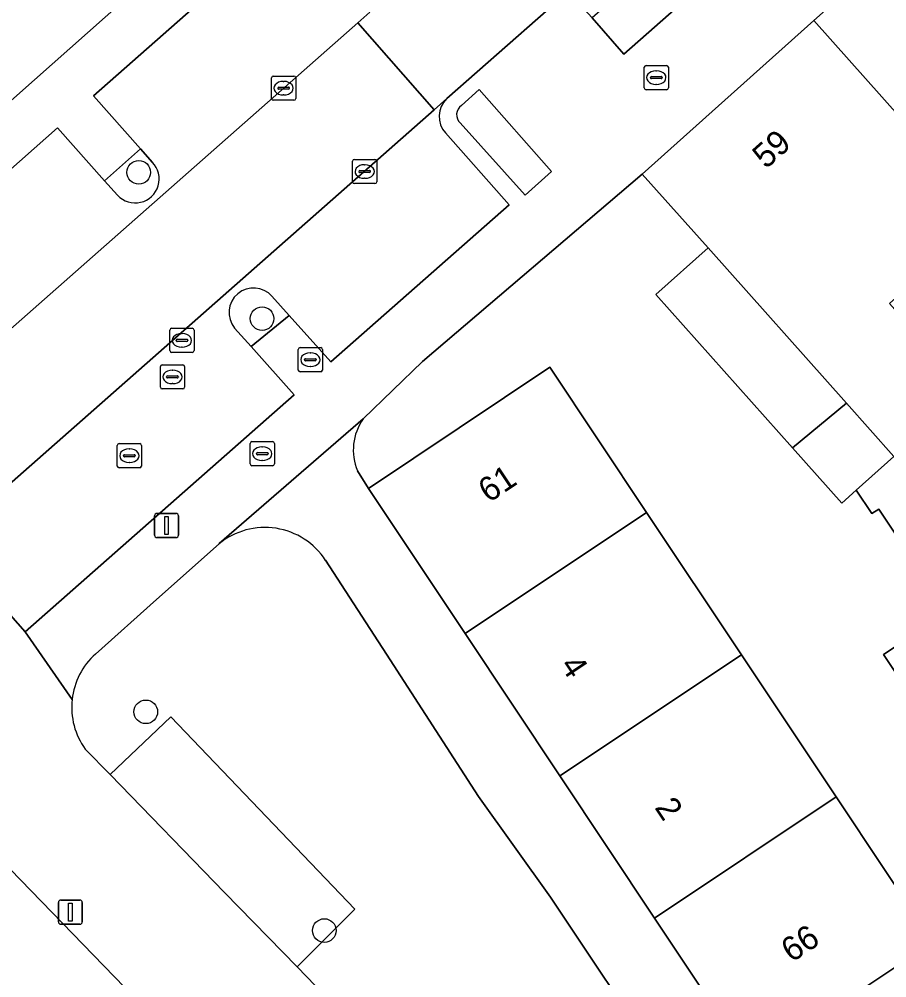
# Model space of a CAD drawing. Extents: x 159960 to 160866, y 382700 to 383354.
# Drawn here: x 160377.49 to 160413.42, y 382879.33 to 382919.01 of the extents above; entities that cross this region are included whole.
import ezdxf

# ---------------------------------------------------------------- set-up
doc = ezdxf.new("R2010")
doc.units = 0
for name, color, linetype in [('IMGEO_Boom', 7, 'Continuous'), ('IMGEO_Brandkraan', 7, 'Continuous'), ('IMGEO_Erf', 7, 'Continuous'), ('IMGEO_Groenvoorziening', 7, 'Continuous'), ('IMGEO_Kolk', 7, 'Continuous'), ('IMGEO_Lichtmast', 7, 'Continuous'), ('IMGEO_Pand', 7, 'Continuous'), ('IMGEO_Pand_nummerreeks', 7, 'Continuous'), ('IMGEO_Parkeervlak_open', 7, 'Continuous'), ('IMGEO_Rijbaan_lokaal_open', 7, 'Continuous'), ('IMGEO_Rioolput', 7, 'Continuous'), ('IMGEO_Voetpad_open', 7, 'Continuous')]:
    doc.layers.add(name, color=color, linetype=linetype)

msp = doc.modelspace()

# ---------------------------------------------------------------- linework, layer by layer
at = {"layer": 'IMGEO_Boom'}
for centre in [(160382.445, 382912.667), (160387.551, 382906.613), (160382.736, 382890.341), (160390.128, 382881.289)]:
    msp.add_circle(centre, 0.489, dxfattribs=at)
at = {"layer": 'IMGEO_Brandkraan'}
for p, q in [((160387.134, 382901.524), (160387.986, 382901.524)), ((160387.059, 382900.598), (160387.059, 382901.45)), ((160387.547, 382901.304), (160387.572, 382901.304)), ((160388.06, 382901.45), (160388.06, 382900.598)), ((160387.318, 382901.018), (160387.318, 382901.03)), ((160387.756, 382900.981), (160387.358, 382900.981)), ((160387.361, 382901.067), (160387.759, 382901.067)), ((160387.57, 382900.744), (160387.545, 382900.744)), ((160387.802, 382901.03), (160387.802, 382901.018)), ((160387.986, 382900.524), (160387.134, 382900.524))]:
    msp.add_line(p, q, dxfattribs=at)
for points in [[(160387.134, 382901.524), (160387.986, 382901.524)], [(160387.059, 382900.598), (160387.059, 382901.45)], [(160388.06, 382901.45), (160388.06, 382900.598)], [(160387.986, 382900.524), (160387.134, 382900.524)]]:
    msp.add_lwpolyline(points, dxfattribs=at)
for centre, radius, start, end in [((160387.136, 382901.448), 0.0765, 91.552, 178.448), ((160387.136, 382901.448), 0.0765, 91.552, 178.448), ((160387.984, 382901.448), 0.0765, 1.552, 88.448), ((160387.984, 382901.448), 0.0765, 1.552, 88.448), ((160387.358, 382901.027), 0.0403, 85.8775, 175.7526), ((160387.355, 382901.017), 0.0366, 178.938, 274.7102), ((160387.759, 382901.024), 0.043, 264.8664, 352.4533), ((160387.763, 382901.029), 0.0386, 1.7309, 96.639), ((160387.136, 382900.6), 0.0765, 181.552, 268.448), ((160387.136, 382900.6), 0.0765, 181.552, 268.448), ((160387.984, 382900.6), 0.0765, 271.552, 358.448), ((160387.984, 382900.6), 0.0765, 271.552, 358.448)]:
    msp.add_arc(centre, radius, start, end, dxfattribs=at)
for centre, major_axis, ratio, start_param, end_param in [((160387.546, 382901.024), (-0.387, 0.002), 0.722429, 4.712389, 7.853982), ((160387.571, 382901.024), (-0.39, 0.002), 0.717154, 1.570796, 4.712389)]:
    msp.add_ellipse(centre, major_axis=major_axis, ratio=ratio, start_param=start_param, end_param=end_param, dxfattribs=at)
at = {"layer": 'IMGEO_Erf'}
for points in [[(160412.146, 382899.51), (160411.554, 382898.982), (160409.515, 382901.266), (160403.856, 382907.606), (160406.019, 382909.536), (160403.288, 382912.595), (160394.188, 382904.838), (160391.732, 382902.464)], [(160391.496, 382900.313), (160391.954, 382899.589), (160399.473, 382904.598), (160403.476, 382898.589), (160407.397, 382892.703), (160411.318, 382886.819), (160415.322, 382880.808), (160408.003, 382875.932), (160409.407, 382875.338)], [(160410.766, 382875.384), (160412.656, 382876.385), (160423.19, 382883.633), (160421.859, 382885.567), (160419.212, 382883.804), (160415.394, 382889.535), (160413.28, 382892.709), (160415.927, 382894.472), (160413.088, 382898.734), (160412.802, 382898.543), (160412.146, 382899.51)]]:
    msp.add_lwpolyline(points, dxfattribs=at)
msp.add_arc((160393.605, 382901.17), 2.276, 145.3568, 202.1207, dxfattribs=at)
at = {"layer": 'IMGEO_Groenvoorziening'}
for points in [[(160366.155, 382905.901), (160381.784, 382919.739)], [(160395.757, 382914.711), (160398.443, 382911.726), (160399.541, 382912.702), (160396.544, 382916.096), (160395.803, 382915.434)], [(160383.011, 382913.08), (160382.519, 382913.635), (160381.031, 382912.321), (160381.57, 382911.719)], [(160386.411, 382906.224), (160387.098, 382905.454), (160388.676, 382906.743), (160387.962, 382907.54)], [(160385.773, 382897.296), (160383.182, 382894.988), (160380.655, 382892.734)], [(160399.496, 382882.677), (160396.518, 382886.833), (160392.707, 382892.722), (160391.172, 382895.093), (160390.183, 382896.611)], [(160380.231, 382888.799), (160381.258, 382887.744), (160383.776, 382890.139), (160391.399, 382882.176), (160389.004, 382879.786), (160390.139, 382878.62), (160398.488, 382870.043)], [(160402.789, 382869.724), (160403.735, 382870.394), (160406.557, 382872.149), (160405.236, 382873.976), (160404.113, 382875.743), (160399.496, 382882.677)]]:
    msp.add_lwpolyline(points, dxfattribs=at)
msp.add_lwpolyline([(160381.258, 382887.744), (160386.001, 382882.871), (160389.004, 382879.786), (160391.399, 382882.176), (160383.776, 382890.139)], close=True, dxfattribs=at)
for centre, radius, start, end in [((160396.068, 382915.054), 0.463, 124.9469, 227.7722), ((160382.299, 382912.391), 0.991, 222.673, 44.0562), ((160387.2, 382906.866), 1.017, 41.4838, 219.1444), ((160387.67, 382894.971), 3, 33.1229, 129.2188), ((160382.623, 382890.529), 2.955, 131.7563, 173.8087), ((160382.612, 382890.531), 2.944, 173.8105, 216.0314)]:
    msp.add_arc(centre, radius, start, end, dxfattribs=at)
at = {"layer": 'IMGEO_Kolk'}
for p, q in [((160403.374, 382916.161), (160403.374, 382917.013)), ((160403.449, 382917.087), (160404.301, 382917.087)), ((160404.375, 382917.013), (160404.375, 382916.161)), ((160387.942, 382915.724), (160387.942, 382916.576)), ((160388.017, 382916.65), (160388.869, 382916.65)), ((160388.943, 382916.576), (160388.943, 382915.724)), ((160403.633, 382916.581), (160403.633, 382916.593)), ((160403.676, 382916.63), (160404.074, 382916.63)), ((160403.862, 382916.867), (160403.887, 382916.867)), ((160404.117, 382916.593), (160404.117, 382916.581)), ((160388.244, 382916.193), (160388.642, 382916.193)), ((160388.43, 382916.43), (160388.455, 382916.43)), ((160404.071, 382916.544), (160403.673, 382916.544)), ((160403.885, 382916.307), (160403.86, 382916.307)), ((160388.201, 382916.144), (160388.201, 382916.156)), ((160388.639, 382916.107), (160388.241, 382916.107)), ((160388.453, 382915.87), (160388.428, 382915.87)), ((160388.685, 382916.156), (160388.685, 382916.144)), ((160404.301, 382916.087), (160403.449, 382916.087)), ((160388.869, 382915.65), (160388.017, 382915.65)), ((160391.3, 382912.275), (160391.3, 382913.127)), ((160391.375, 382913.201), (160392.227, 382913.201)), ((160392.301, 382913.127), (160392.301, 382912.275)), ((160391.559, 382912.695), (160391.559, 382912.707)), ((160391.997, 382912.658), (160391.599, 382912.658)), ((160391.602, 382912.744), (160392, 382912.744)), ((160391.788, 382912.981), (160391.813, 382912.981)), ((160392.043, 382912.707), (160392.043, 382912.695)), ((160392.227, 382912.201), (160391.375, 382912.201)), ((160391.811, 382912.421), (160391.786, 382912.421))]:
    msp.add_line(p, q, dxfattribs=at)
for points in [[(160403.374, 382916.161), (160403.374, 382917.013)], [(160403.449, 382917.087), (160404.301, 382917.087)], [(160404.375, 382917.013), (160404.375, 382916.161)], [(160387.942, 382915.724), (160387.942, 382916.576)], [(160388.017, 382916.65), (160388.869, 382916.65)], [(160388.943, 382916.576), (160388.943, 382915.724)], [(160404.301, 382916.087), (160403.449, 382916.087)], [(160388.869, 382915.65), (160388.017, 382915.65)], [(160391.3, 382912.275), (160391.3, 382913.127)], [(160391.375, 382913.201), (160392.227, 382913.201)], [(160392.301, 382913.127), (160392.301, 382912.275)], [(160392.227, 382912.201), (160391.375, 382912.201)]]:
    msp.add_lwpolyline(points, dxfattribs=at)
for centre, radius, start, end in [((160403.451, 382917.011), 0.0765, 91.552, 178.448), ((160403.451, 382917.011), 0.0765, 91.552, 178.448), ((160404.299, 382917.011), 0.0765, 1.552, 88.448), ((160404.299, 382917.011), 0.0765, 1.552, 88.448), ((160388.019, 382916.574), 0.0765, 91.552, 178.448), ((160388.019, 382916.574), 0.0765, 91.552, 178.448), ((160388.867, 382916.574), 0.0765, 1.552, 88.448), ((160388.867, 382916.574), 0.0765, 1.552, 88.448), ((160403.673, 382916.59), 0.0403, 85.8775, 175.7526), ((160403.67, 382916.58), 0.0366, 178.938, 274.7102), ((160404.074, 382916.587), 0.043, 264.8664, 352.4533), ((160404.078, 382916.592), 0.0386, 1.7309, 96.639), ((160388.241, 382916.153), 0.0403, 85.8775, 175.7526), ((160388.646, 382916.155), 0.0386, 1.7309, 96.639), ((160388.238, 382916.143), 0.0366, 178.938, 274.7102), ((160388.642, 382916.15), 0.043, 264.8664, 352.4533), ((160403.451, 382916.163), 0.0765, 181.552, 268.448), ((160403.451, 382916.163), 0.0765, 181.552, 268.448), ((160404.299, 382916.163), 0.0765, 271.552, 358.448), ((160404.299, 382916.163), 0.0765, 271.552, 358.448), ((160388.019, 382915.726), 0.0765, 181.552, 268.448), ((160388.019, 382915.726), 0.0765, 181.552, 268.448), ((160388.867, 382915.726), 0.0765, 271.552, 358.448), ((160388.867, 382915.726), 0.0765, 271.552, 358.448), ((160391.377, 382913.125), 0.0765, 91.552, 178.448), ((160391.377, 382913.125), 0.0765, 91.552, 178.448), ((160392.225, 382913.125), 0.0765, 1.552, 88.448), ((160392.225, 382913.125), 0.0765, 1.552, 88.448), ((160391.599, 382912.704), 0.0403, 85.8775, 175.7526), ((160391.596, 382912.694), 0.0366, 178.938, 274.7102), ((160392, 382912.701), 0.043, 264.8664, 352.4533), ((160392.004, 382912.706), 0.0386, 1.7309, 96.639), ((160391.377, 382912.277), 0.0765, 181.552, 268.448), ((160391.377, 382912.277), 0.0765, 181.552, 268.448), ((160392.225, 382912.277), 0.0765, 271.552, 358.448), ((160392.225, 382912.277), 0.0765, 271.552, 358.448)]:
    msp.add_arc(centre, radius, start, end, dxfattribs=at)
for centre, major_axis, ratio, start_param, end_param in [((160403.861, 382916.587), (-0.387, 0.002), 0.722429, 4.712389, 7.853982), ((160403.886, 382916.587), (-0.39, 0.002), 0.717154, 1.570796, 4.712389), ((160388.429, 382916.15), (-0.387, 0.002), 0.722429, 4.712389, 7.853982), ((160388.454, 382916.15), (-0.39, 0.002), 0.717154, 1.570796, 4.712389), ((160391.787, 382912.701), (-0.387, 0.002), 0.722429, 4.712389, 7.853982), ((160391.812, 382912.701), (-0.39, 0.002), 0.717154, 1.570796, 4.712389)]:
    msp.add_ellipse(centre, major_axis=major_axis, ratio=ratio, start_param=start_param, end_param=end_param, dxfattribs=at)
at = {"layer": 'IMGEO_Lichtmast'}
for p, q in [((160383.099, 382897.652), (160383.099, 382898.452)), ((160383.099, 382898.452), (160383.099, 382897.652)), ((160383.199, 382898.552), (160383.989, 382898.552)), ((160383.989, 382898.552), (160383.199, 382898.552)), ((160384.089, 382898.452), (160384.089, 382897.652)), ((160384.089, 382897.652), (160384.089, 382898.452)), ((160383.989, 382897.552), (160383.199, 382897.552)), ((160383.199, 382897.552), (160383.989, 382897.552)), ((160379.118, 382881.652), (160379.118, 382882.452)), ((160379.118, 382882.452), (160379.118, 382881.652)), ((160379.218, 382882.552), (160380.008, 382882.552)), ((160380.008, 382882.552), (160379.218, 382882.552)), ((160380.108, 382882.452), (160380.108, 382881.652)), ((160380.108, 382881.652), (160380.108, 382882.452)), ((160380.008, 382881.552), (160379.218, 382881.552)), ((160379.218, 382881.552), (160380.008, 382881.552))]:
    msp.add_line(p, q, dxfattribs=at)
for points in [[(160383.519, 382898.427), (160383.669, 382898.427), (160383.669, 382897.677), (160383.519, 382897.677), (160383.519, 382898.427)], [(160379.538, 382882.427), (160379.688, 382882.427), (160379.688, 382881.677), (160379.538, 382881.677), (160379.538, 382882.427)]]:
    msp.add_lwpolyline(points, dxfattribs=at)
for centre, start, end in [((160383.199, 382898.452), 90, 180), ((160383.199, 382898.452), 90, 180), ((160383.989, 382898.452), 0, 90), ((160383.989, 382898.452), 360, 90), ((160383.199, 382897.652), 180, 270), ((160383.199, 382897.652), 180, 270), ((160383.989, 382897.652), 270, 0), ((160383.989, 382897.652), 270, 0), ((160379.218, 382882.452), 90, 180), ((160379.218, 382882.452), 90, 180), ((160380.008, 382882.452), 0, 90), ((160380.008, 382882.452), 360, 90), ((160379.218, 382881.652), 180, 270), ((160379.218, 382881.652), 180, 270), ((160380.008, 382881.652), 270, 0), ((160380.008, 382881.652), 270, 0)]:
    msp.add_arc(centre, 0.1, start, end, dxfattribs=at)
at = {"layer": 'IMGEO_Pand'}
for points in [[(160417.607, 382910.873), (160421.775, 382914.592), (160414.86, 382922.319), (160413.693, 382921.277), (160413.048, 382921.313), (160410.404, 382918.951)], [(160417.607, 382910.873), (160410.404, 382918.951), (160403.288, 382912.595), (160406.019, 382909.536), (160411.744, 382903.119), (160413.715, 382900.91), (160414.009, 382900.58), (160417.048, 382903.292), (160416.754, 382903.621), (160416.577, 382903.82), (160413.528, 382907.233)], [(160409.515, 382901.266), (160411.744, 382903.119), (160406.019, 382909.536), (160403.856, 382907.606)], [(160403.476, 382898.589), (160399.473, 382904.598), (160391.954, 382899.589), (160395.958, 382893.579)], [(160411.744, 382903.119), (160409.515, 382901.266), (160411.554, 382898.982), (160412.146, 382899.51), (160413.715, 382900.91)], [(160399.878, 382887.694), (160407.397, 382892.703), (160403.476, 382898.589), (160395.958, 382893.579)], [(160415.394, 382889.535), (160418.041, 382891.298), (160415.927, 382894.472), (160413.28, 382892.709)], [(160399.878, 382887.694), (160403.799, 382881.809), (160411.318, 382886.819), (160407.397, 382892.703)], [(160411.318, 382886.819), (160403.799, 382881.809), (160407.803, 382875.799), (160408.003, 382875.932), (160415.322, 382880.808)]]:
    msp.add_lwpolyline(points, close=True, dxfattribs=at)
at = {"layer": 'IMGEO_Parkeervlak_open'}
for points in [[(160390.603, 382919.386), (160387.951, 382922.339), (160380.575, 382915.828), (160382.519, 382913.635), (160383.011, 382913.08)], [(160391.511, 382918.854), (160392.017, 382919.3)], [(160370.583, 382900.414), (160391.511, 382918.854)], [(160395.198, 382915.717), (160394.678, 382915.259), (160373.704, 382896.786)], [(160381.57, 382911.719), (160381.031, 382912.321), (160379.078, 382914.503), (160367.938, 382904.662), (160370.607, 382901.713)], [(160387.962, 382907.54), (160388.676, 382906.743), (160390.397, 382904.824), (160397.788, 382911.328), (160395.148, 382914.297)], [(160387.098, 382905.454), (160386.411, 382906.224)], [(160375.1, 382896.628), (160377.736, 382893.648), (160388.876, 382903.461), (160387.098, 382905.454)]]:
    msp.add_lwpolyline(points, dxfattribs=at)
msp.add_lwpolyline([(160404.693, 382922.117), (160401.213, 382919.063), (160402.526, 382917.553), (160405.993, 382920.62)], close=True, dxfattribs=at)
for centre, radius, start, end in [((160395.89, 382914.982), 1.01, 133.2732, 222.6936), ((160382.299, 382912.391), 0.991, 222.673, 44.0562), ((160387.2, 382906.866), 1.017, 41.4838, 219.1444)]:
    msp.add_arc(centre, radius, start, end, dxfattribs=at)
at = {"layer": 'IMGEO_Rijbaan_lokaal_open'}
for points in [[(160392.017, 382919.3), (160391.511, 382918.854), (160394.678, 382915.259), (160395.198, 382915.717), (160400.229, 382920.15)], [(160395.536, 382864.921), (160393.904, 382866.524), (160375.822, 382885.157), (160373.661, 382887.411), (160370.355, 382884.103), (160401.781, 382852.143)]]:
    msp.add_lwpolyline(points, dxfattribs=at)
msp.add_lwpolyline([(160391.511, 382918.854), (160370.583, 382900.414), (160370.468, 382900.311), (160373.704, 382896.786), (160394.678, 382915.259)], close=True, dxfattribs=at)
at = {"layer": 'IMGEO_Rioolput'}
for p, q in [((160383.732, 382905.288), (160383.732, 382906.14)), ((160383.807, 382906.214), (160384.659, 382906.214)), ((160384.22, 382905.994), (160384.245, 382905.994)), ((160384.733, 382906.14), (160384.733, 382905.288)), ((160383.991, 382905.708), (160383.991, 382905.72)), ((160384.429, 382905.671), (160384.031, 382905.671)), ((160384.034, 382905.757), (160384.432, 382905.757)), ((160384.475, 382905.72), (160384.475, 382905.708)), ((160384.659, 382905.214), (160383.807, 382905.214)), ((160384.243, 382905.434), (160384.218, 382905.434)), ((160389.051, 382904.487), (160389.051, 382905.339)), ((160389.126, 382905.413), (160389.978, 382905.413)), ((160389.539, 382905.193), (160389.564, 382905.193)), ((160390.052, 382905.339), (160390.052, 382904.487)), ((160383.416, 382904.702), (160384.268, 382904.702)), ((160389.31, 382904.907), (160389.31, 382904.919)), ((160389.748, 382904.87), (160389.35, 382904.87)), ((160389.353, 382904.956), (160389.751, 382904.956)), ((160389.794, 382904.919), (160389.794, 382904.907)), ((160383.341, 382903.776), (160383.341, 382904.628)), ((160383.829, 382904.482), (160383.854, 382904.482)), ((160384.342, 382904.628), (160384.342, 382903.776)), ((160389.978, 382904.413), (160389.126, 382904.413)), ((160389.562, 382904.633), (160389.537, 382904.633)), ((160383.6, 382904.196), (160383.6, 382904.208)), ((160384.038, 382904.159), (160383.64, 382904.159)), ((160383.643, 382904.245), (160384.041, 382904.245)), ((160383.852, 382903.922), (160383.827, 382903.922)), ((160384.084, 382904.208), (160384.084, 382904.196)), ((160384.268, 382903.702), (160383.416, 382903.702)), ((160381.557, 382900.513), (160381.557, 382901.365)), ((160381.632, 382901.439), (160382.484, 382901.439)), ((160382.045, 382901.219), (160382.07, 382901.219)), ((160382.558, 382901.365), (160382.558, 382900.513)), ((160381.816, 382900.933), (160381.816, 382900.945)), ((160382.254, 382900.896), (160381.856, 382900.896)), ((160381.859, 382900.982), (160382.257, 382900.982)), ((160382.3, 382900.945), (160382.3, 382900.933)), ((160382.484, 382900.439), (160381.632, 382900.439)), ((160382.068, 382900.659), (160382.043, 382900.659))]:
    msp.add_line(p, q, dxfattribs=at)
for points in [[(160383.732, 382905.288), (160383.732, 382906.14)], [(160383.807, 382906.214), (160384.659, 382906.214)], [(160384.733, 382906.14), (160384.733, 382905.288)], [(160384.659, 382905.214), (160383.807, 382905.214)], [(160389.051, 382904.487), (160389.051, 382905.339)], [(160389.126, 382905.413), (160389.978, 382905.413)], [(160390.052, 382905.339), (160390.052, 382904.487)], [(160383.416, 382904.702), (160384.268, 382904.702)], [(160383.341, 382903.776), (160383.341, 382904.628)], [(160384.342, 382904.628), (160384.342, 382903.776)], [(160389.978, 382904.413), (160389.126, 382904.413)], [(160384.268, 382903.702), (160383.416, 382903.702)], [(160381.557, 382900.513), (160381.557, 382901.365)], [(160381.632, 382901.439), (160382.484, 382901.439)], [(160382.558, 382901.365), (160382.558, 382900.513)], [(160382.484, 382900.439), (160381.632, 382900.439)]]:
    msp.add_lwpolyline(points, dxfattribs=at)
for centre, radius, start, end in [((160383.809, 382906.138), 0.0765, 91.552, 178.448), ((160383.809, 382906.138), 0.0765, 91.552, 178.448), ((160384.657, 382906.138), 0.0765, 1.552, 88.448), ((160384.657, 382906.138), 0.0765, 1.552, 88.448), ((160384.031, 382905.717), 0.0403, 85.8775, 175.7526), ((160384.028, 382905.707), 0.0366, 178.938, 274.7102), ((160384.432, 382905.714), 0.043, 264.8664, 352.4533), ((160384.436, 382905.719), 0.0386, 1.7309, 96.639), ((160383.809, 382905.29), 0.0765, 181.552, 268.448), ((160383.809, 382905.29), 0.0765, 181.552, 268.448), ((160384.657, 382905.29), 0.0765, 271.552, 358.448), ((160384.657, 382905.29), 0.0765, 271.552, 358.448), ((160389.128, 382905.337), 0.0765, 91.552, 178.448), ((160389.128, 382905.337), 0.0765, 91.552, 178.448), ((160389.976, 382905.337), 0.0765, 1.552, 88.448), ((160389.976, 382905.337), 0.0765, 1.552, 88.448), ((160383.418, 382904.626), 0.0765, 91.552, 178.448), ((160383.418, 382904.626), 0.0765, 91.552, 178.448), ((160384.266, 382904.626), 0.0765, 1.552, 88.448), ((160384.266, 382904.626), 0.0765, 1.552, 88.448), ((160389.35, 382904.916), 0.0403, 85.8775, 175.7526), ((160389.347, 382904.906), 0.0366, 178.938, 274.7102), ((160389.751, 382904.913), 0.043, 264.8664, 352.4533), ((160389.755, 382904.918), 0.0386, 1.7309, 96.639), ((160389.128, 382904.489), 0.0765, 181.552, 268.448), ((160389.128, 382904.489), 0.0765, 181.552, 268.448), ((160389.976, 382904.489), 0.0765, 271.552, 358.448), ((160389.976, 382904.489), 0.0765, 271.552, 358.448), ((160383.64, 382904.205), 0.0403, 85.8775, 175.7526), ((160383.637, 382904.195), 0.0366, 178.938, 274.7102), ((160384.041, 382904.202), 0.043, 264.8664, 352.4533), ((160384.045, 382904.207), 0.0386, 1.7309, 96.639), ((160383.418, 382903.778), 0.0765, 181.552, 268.448), ((160383.418, 382903.778), 0.0765, 181.552, 268.448), ((160384.266, 382903.778), 0.0765, 271.552, 358.448), ((160384.266, 382903.778), 0.0765, 271.552, 358.448), ((160381.634, 382901.363), 0.0765, 91.552, 178.448), ((160381.634, 382901.363), 0.0765, 91.552, 178.448), ((160382.482, 382901.363), 0.0765, 1.552, 88.448), ((160382.482, 382901.363), 0.0765, 1.552, 88.448), ((160381.856, 382900.942), 0.0403, 85.8775, 175.7526), ((160381.853, 382900.932), 0.0366, 178.938, 274.7102), ((160382.257, 382900.939), 0.043, 264.8664, 352.4533), ((160382.261, 382900.944), 0.0386, 1.7309, 96.639), ((160381.634, 382900.515), 0.0765, 181.552, 268.448), ((160381.634, 382900.515), 0.0765, 181.552, 268.448), ((160382.482, 382900.515), 0.0765, 271.552, 358.448), ((160382.482, 382900.515), 0.0765, 271.552, 358.448)]:
    msp.add_arc(centre, radius, start, end, dxfattribs=at)
for centre, major_axis, ratio, start_param, end_param in [((160384.219, 382905.714), (-0.387, 0.002), 0.722429, 4.712389, 7.853982), ((160384.244, 382905.714), (-0.39, 0.002), 0.717154, 1.570796, 4.712389), ((160389.538, 382904.913), (-0.387, 0.002), 0.722429, 4.712389, 7.853982), ((160389.563, 382904.913), (-0.39, 0.002), 0.717154, 1.570796, 4.712389), ((160383.828, 382904.202), (-0.387, 0.002), 0.722429, 4.712389, 7.853982), ((160383.853, 382904.202), (-0.39, 0.002), 0.717154, 1.570796, 4.712389), ((160382.044, 382900.939), (-0.387, 0.002), 0.722429, 4.712389, 7.853982), ((160382.069, 382900.939), (-0.39, 0.002), 0.717154, 1.570796, 4.712389)]:
    msp.add_ellipse(centre, major_axis=major_axis, ratio=ratio, start_param=start_param, end_param=end_param, dxfattribs=at)
at = {"layer": 'IMGEO_Voetpad_open'}
for points in [[(160410.637, 382927.449), (160410.535, 382927.384), (160410.264, 382927.197), (160410.161, 382927.105), (160410.265, 382927.005), (160409.057, 382925.947), (160410.357, 382924.482), (160406.9, 382921.414), (160405.592, 382922.909), (160404.693, 382922.117), (160405.993, 382920.62), (160402.526, 382917.553), (160401.213, 382919.063), (160400.229, 382920.15), (160395.198, 382915.717)], [(160389.776, 382926.795), (160382.706, 382920.553), (160381.784, 382919.739), (160366.155, 382905.901)], [(160370.607, 382901.713), (160367.938, 382904.662), (160379.078, 382914.503), (160381.031, 382912.321), (160382.519, 382913.635), (160380.575, 382915.828), (160387.951, 382922.339)], [(160394.188, 382904.838), (160403.288, 382912.595), (160410.404, 382918.951), (160413.048, 382921.313), (160413.693, 382921.277)], [(160395.803, 382915.434), (160396.544, 382916.096), (160399.541, 382912.702), (160398.443, 382911.726), (160395.757, 382914.711)], [(160395.148, 382914.297), (160397.788, 382911.328), (160390.397, 382904.824), (160388.676, 382906.743), (160387.098, 382905.454), (160388.876, 382903.461), (160377.736, 382893.648), (160379.685, 382890.848)], [(160380.655, 382892.734), (160383.182, 382894.988), (160385.773, 382897.296), (160385.779, 382897.302), (160391.732, 382902.464), (160394.188, 382904.838)], [(160391.732, 382902.464), (160385.779, 382897.302), (160385.773, 382897.296)], [(160413.715, 382900.91), (160412.146, 382899.51), (160412.802, 382898.543), (160413.088, 382898.734), (160415.927, 382894.472)], [(160395.958, 382893.579), (160391.954, 382899.589), (160391.496, 382900.313)], [(160379.685, 382890.848), (160377.736, 382893.648), (160375.1, 382896.628)], [(160390.183, 382896.611), (160391.172, 382895.093), (160392.707, 382892.722), (160396.518, 382886.833), (160399.496, 382882.677), (160404.113, 382875.743), (160405.236, 382873.976), (160406.557, 382872.149), (160412.656, 382876.385), (160410.766, 382875.384)], [(160409.407, 382875.338), (160408.003, 382875.932), (160407.803, 382875.799), (160403.799, 382881.809), (160399.878, 382887.694), (160395.958, 382893.579)], [(160389.004, 382879.786), (160386.001, 382882.871), (160381.258, 382887.744), (160380.231, 382888.799)], [(160373.248, 382887.823), (160373.661, 382887.411), (160375.822, 382885.157), (160393.904, 382866.524), (160395.536, 382864.921)], [(160398.488, 382870.043), (160390.139, 382878.62), (160389.004, 382879.786)]]:
    msp.add_lwpolyline(points, dxfattribs=at)
for centre, radius, start, end in [((160395.89, 382914.982), 1.01, 133.2732, 222.6936), ((160396.068, 382915.054), 0.463, 124.9469, 227.7722), ((160393.605, 382901.17), 2.276, 145.3568, 202.1207), ((160387.67, 382894.971), 3, 33.1229, 129.2188), ((160382.623, 382890.529), 2.955, 131.7563, 173.8087), ((160382.612, 382890.531), 2.944, 173.8105, 216.0314)]:
    msp.add_arc(centre, radius, start, end, dxfattribs=at)

# ---------------------------------------------------------------- texts
at = {"layer": 'IMGEO_Pand_nummerreeks'}
for s, rotation, p in [('59', 41.7744, (160408.415, 382912.776)), ('61', 33.6707, (160396.938, 382898.968)), ('4', 303.6717, (160399.862, 382892.263)), ('2', 303.6717, (160403.782, 382886.379)), ('66', 33.6707, (160409.478, 382879.943))]:
    msp.add_text(s, height=1, rotation=rotation, dxfattribs=at).set_placement(p)

doc.saveas('drawing.dxf')
